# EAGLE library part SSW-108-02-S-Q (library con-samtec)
THROUGH-HOLE .025" SQ POST SOCKET Source: Samtec SSW.pdf
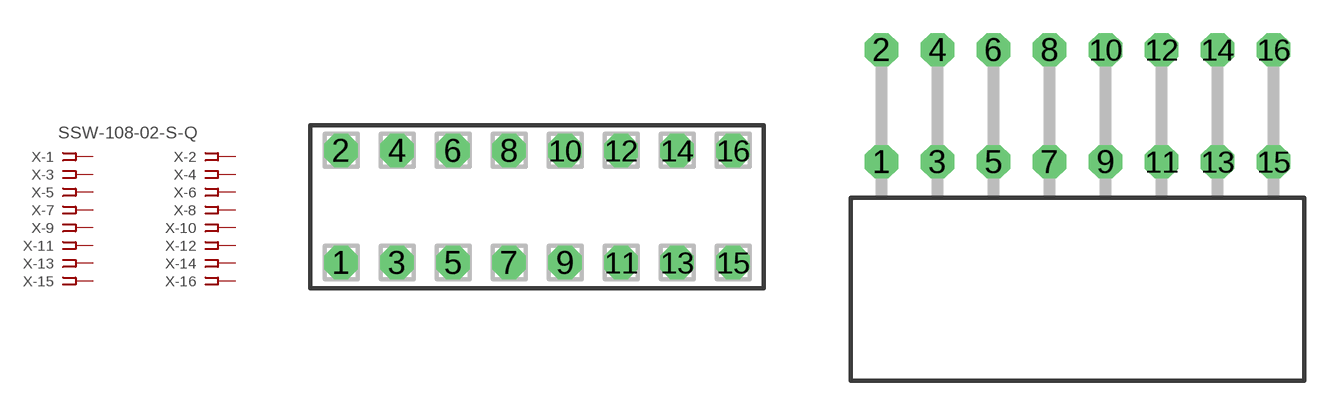
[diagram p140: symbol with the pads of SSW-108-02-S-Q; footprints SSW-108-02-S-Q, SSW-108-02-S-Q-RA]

Designator prefix X; gates -1=FPINV -2=FPIN -3=FPIN -4=FPIN -5=FPIN -6=FPIN -7=FPIN -8=FPIN -9=FPIN -10=FPIN -11=FPIN -12=FPIN -13=FPIN -14=FPIN -15=FPIN -16=FPIN

## SSW-108-02-S-Q (MPN: SSW-108-02-S-Q; OC_FARNELL: unknown; OC_NEWARK: 82P4347)  [SSW-108-02-S-Q]
1  -1:1  pas
2  -2:1  pas
3  -3:1  pas
4  -4:1  pas
5  -5:1  pas
6  -6:1  pas
7  -7:1  pas
8  -8:1  pas
9  -9:1  pas
10  -10:1  pas
11  -11:1  pas
12  -12:1  pas
13  -13:1  pas
14  -14:1  pas
15  -15:1  pas
16  -16:1  pas

## SSW-108-02-S-QRA (MPN: SSW-108-02-S-Q-RA; OC_FARNELL: unknown; OC_NEWARK: 82P4348)  [SSW-108-02-S-Q-RA]
Pads as for SSW-108-02-S-Q

## Footprint SSW-108-02-S-Q (pad centres in mm)
THROUGH-HOLE .025" SQ POST SOCKET Source: Samtec SSW.pdf
drill 1 pad 1.5 octagon: 1 -8.89,-2.54; 2 -8.89,2.54; 3 -6.35,-2.54; 4 -6.35,2.54; 5 -3.81,-2.54; 6 -3.81,2.54; 7 -1.27,-2.54; 8 -1.27,2.54; 9 1.27,-2.54; 10 1.27,2.54; 11 3.81,-2.54; 12 3.81,2.54; 13 6.35,-2.54; 14 6.35,2.54; 15 8.89,-2.54; 16 8.89,2.54

## Footprint SSW-108-02-S-Q-RA (pad centres in mm)
THROUGH-HOLE .025" SQ POST SOCKET Source: Samtec SSW.pdf
drill 1 pad 1.5 octagon: 1 -8.89,1.524; 2 -8.89,6.604; 3 -6.35,1.524; 4 -6.35,6.604; 5 -3.81,1.524; 6 -3.81,6.604; 7 -1.27,1.524; 8 -1.27,6.604; 9 1.27,1.524; 10 1.27,6.604; 11 3.81,1.524; 12 3.81,6.604; 13 6.35,1.524; 14 6.35,6.604; 15 8.89,1.524; 16 8.89,6.604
